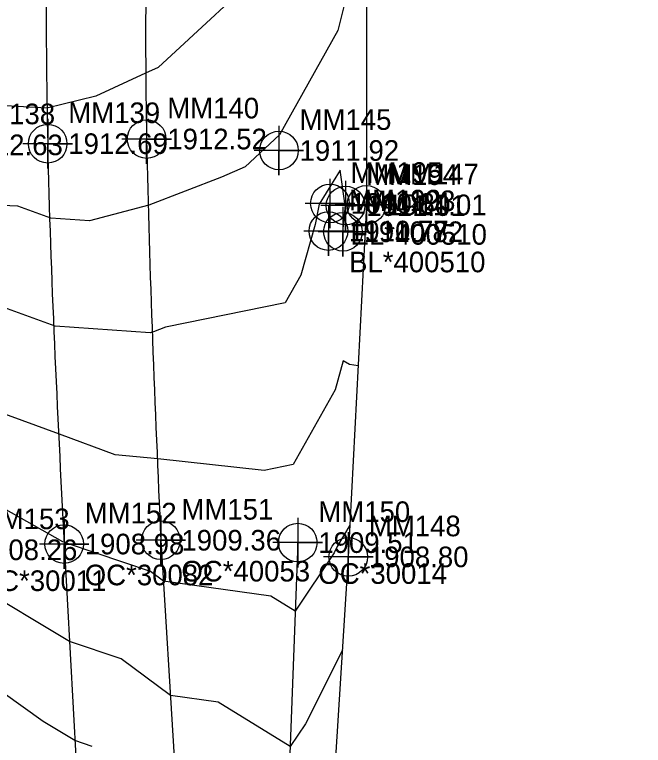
# Model space of a CAD drawing. Extents: x 1004378 to 1005103, y 553854 to 554288.
# Drawn here: x 1005009.8 to 1005086, y 554030.8 to 554119.4 of the extents above; entities that cross this region are included whole.
import ezdxf

# ---------------------------------------------------------------- set-up
doc = ezdxf.new("R2010")
doc.units = 0
for name, color, linetype in [('DTM Contours Major', 7, 'Continuous'), ('DTM Contours Minor', 7, 'Continuous'), ('Exist DTM Breakline', 7, 'Continuous'), ('Exist DTM Breakline Cogo Comment', 7, 'Continuous'), ('Exist DTM Breakline Cogo Elevation', 7, 'Continuous'), ('Exist DTM Breakline Cogo Number', 7, 'Continuous'), ('Exist DTM Breakline Cogo Point CELL', 7, 'Continuous'), ('Exist DTM Crownline', 7, 'Continuous'), ('Exist DTM Crownline Cogo Comment', 7, 'Continuous'), ('Exist DTM Crownline Cogo Elevation', 7, 'Continuous'), ('Exist DTM Crownline Cogo Number', 7, 'Continuous'), ('Exist DTM Crownline Cogo Point CELL', 7, 'Continuous'), ('Exist Roads EOP', 7, 'Continuous'), ('Exist Roads EOP Cogo Comment', 7, 'Continuous'), ('Exist Roads EOP Cogo Elevation', 7, 'Continuous'), ('Exist Roads EOP Cogo Number', 7, 'Continuous'), ('Exist Roads EOP Cogo Point CELL', 7, 'Continuous')]:
    doc.layers.add(name, color=color, linetype=linetype)

msp = doc.modelspace()

# ---------------------------------------------------------------- linework, layer by layer
at = {"layer": 'DTM Contours Major'}
msp.add_lwpolyline([(1005051.433, 554076.836), (1005050.379, 554076.997), (1005049.638, 554077.419), (1005048.654, 554073.906), (1005043.562, 554064.845), (1005040.05, 554064.129), (1005027.148, 554065.55), (1005021.967, 554066.02), (1005015.22, 554068.538), (1005006.107, 554071.836), (1005002.083, 554074.095), (1005000.368, 554076.389), (1005000.016, 554076.907), (1004996.136, 554080.152), (1004993.696, 554082.636), (1004992.74, 554083.442), (1004991.884, 554081.943), (1004990.65, 554081.337), (1004990.87, 554080.789), (1004991.142, 554080.251), (1004992.761, 554070.753), (1004992.29, 554066.815), (1004992.25, 554064.983), (1004991.398, 554057.275)], dxfattribs=at)
at = {"layer": 'DTM Contours Minor'}
for points in [[(1005052.451, 554131.423), (1005048.992, 554117.484), (1005041.887, 554104.823), (1005037.717, 554100.961), (1005034.877, 554099.678), (1005026.061, 554096.307), (1005018.838, 554094.398), (1005014.143, 554094.731), (1005010.132, 554096.182), (1005001.278, 554096.56)], [(1005041.535, 554126.294), (1005027.186, 554113.002), (1005025.646, 554112.306), (1005019.626, 554109.515), (1005013.669, 554108.071), (1005006.504, 554108.468), (1005001.004, 554108.005), (1004994.526, 554114.001), (1004990.716, 554115.591), (1004987.329, 554111.605), (1004985.839, 554106.502), (1004985.665, 554106.048), (1004985.362, 554104.451), (1004983.277, 554088.12), (1004983.322, 554088.07), (1004988.078, 554078.655), (1004989.286, 554071.569), (1004988.935, 554068.632), (1004988.827, 554063.674), (1004986.946, 554046.675), (1004985.61, 554041.811), (1004986.291, 554040.195), (1004985.892, 554032.658), (1004985.548, 554017.288)], [(1005052.429, 554096.185), (1005052.32, 554096.202), (1005049.904, 554096.144), (1005049.861, 554096.167), (1005049.846, 554096.257), (1005049.276, 554100.535), (1005046.713, 554096.403), (1005046.211, 554093.964), (1005044.49, 554087.817), (1005042.6, 554084.453), (1005028.071, 554081.489), (1005026.605, 554080.928), (1005026.192, 554080.819), (1005014.682, 554081.634), (1005004.85, 554085.192)], [(1005050.437, 554057.486), (1005048.879, 554054.931), (1005048.518, 554054.142), (1005043.793, 554047.065), (1005040.855, 554048.876), (1005027.803, 554050.713), (1005026.234, 554051.882), (1005016.31, 554055.236), (1005015.759, 554055.441), (1005015.604, 554055.497), (1005002.486, 554062.863), (1004996.894, 554070.341), (1004995.745, 554072.029), (1004993.918, 554073.557), (1004993.443, 554073.279), (1004993.92, 554070.481), (1004993.409, 554066.21), (1004993.392, 554065.419), (1004990.679, 554040.901), (1004990.057, 554038.638), (1004990.374, 554037.886), (1004989.848, 554027.938)], [(1005049.523, 554042.345), (1005045.034, 554033.434), (1005043.176, 554030.651), (1005034.444, 554036.034), (1005028.658, 554036.849), (1005022.704, 554041.282), (1005016.415, 554043.408), (1005004.921, 554050.257), (1005002.926, 554051.684), (1005001.954, 554052.767), (1004994.229, 554063.106), (1004991.612, 554039.458), (1004991.169, 554037.845), (1004991.395, 554037.308), (1004990.837, 554026.758)], [(1005019.174, 554030.683), (1005017.072, 554031.393), (1005013.231, 554033.682), (1005003.473, 554040.664), (1004998.719, 554045.96), (1004994.107, 554052.132), (1004992.545, 554038.014), (1004992.281, 554037.051), (1004992.416, 554036.731), (1004991.826, 554025.578)]]:
    msp.add_lwpolyline(points, dxfattribs=at)
at = {"layer": 'Exist DTM Breakline'}
msp.add_line((1005027.497, 554055.674), (1005030.119, 554013.168), dxfattribs=at)
for points in [[(1005086.044, 554233.622), (1005066.807, 554200.26), (1005058.407, 554172.308), (1005052.455, 554140.645), (1005052.437, 554096.336), (1005050.24, 554053.656), (1005047.48, 554010.1), (1005047.57, 553964.54), (1005045.226, 553915.523), (1005033.752, 553871.735)], [(1005047.836, 554093.162), (1005049.592, 554093.078), (1005049.914, 554096.247), (1005048.016, 554096.507)]]:
    msp.add_lwpolyline(points, dxfattribs=at)
msp.add_spline([(1005062.556, 554249.275), (1005041.97, 554212.824), (1005032.11, 554179.915), (1005026.833, 554146.301), (1005025.779, 554104.318), (1005027.497, 554055.674)], degree=3, dxfattribs=at)
at = {"layer": 'Exist DTM Breakline Cogo Point CELL'}
for points in [[(1005025.779, 554107.318), (1005025.779, 554101.318), (1005025.779, 554104.318), (1005028.779, 554104.318), (1005022.779, 554104.318)], [(1005048.016, 554099.507), (1005048.016, 554093.507), (1005048.016, 554096.507), (1005051.016, 554096.507), (1005045.016, 554096.507)], [(1005049.914, 554099.247), (1005049.914, 554093.247), (1005049.914, 554096.247), (1005052.914, 554096.247), (1005046.914, 554096.247)], [(1005052.437, 554099.336), (1005052.437, 554093.336), (1005052.437, 554096.336), (1005055.437, 554096.336), (1005049.437, 554096.336)], [(1005047.836, 554096.162), (1005047.836, 554090.162), (1005047.836, 554093.162), (1005050.836, 554093.162), (1005044.836, 554093.162)], [(1005049.592, 554096.078), (1005049.592, 554090.078), (1005049.592, 554093.078), (1005052.592, 554093.078), (1005046.592, 554093.078)], [(1005027.497, 554058.674), (1005027.497, 554052.674), (1005027.497, 554055.674), (1005030.497, 554055.674), (1005024.497, 554055.674)], [(1005050.24, 554056.656), (1005050.24, 554050.656), (1005050.24, 554053.656), (1005053.24, 554053.656), (1005047.24, 554053.656)]]:
    msp.add_lwpolyline(points, dxfattribs=at)
for centre in [(1005025.779, 554104.318), (1005048.016, 554096.507), (1005049.914, 554096.247), (1005052.437, 554096.336), (1005047.836, 554093.162), (1005049.592, 554093.078), (1005027.497, 554055.674), (1005050.24, 554053.656)]:
    msp.add_circle(centre, 2.344, dxfattribs=at)
at = {"layer": 'Exist DTM Crownline'}
msp.add_line((1005015.769, 554055.214), (1005018.108, 554012.47), dxfattribs=at)
msp.add_spline([(1005050.587, 554258.044), (1005028.479, 554219.945), (1005017.046, 554183.931), (1005013.967, 554147.492), (1005013.771, 554103.753), (1005015.769, 554055.214)], degree=3, dxfattribs=at)
at = {"layer": 'Exist DTM Crownline Cogo Point CELL'}
for points in [[(1005013.771, 554106.753), (1005013.771, 554100.753), (1005013.771, 554103.753), (1005016.771, 554103.753), (1005010.771, 554103.753)], [(1005015.769, 554058.214), (1005015.769, 554052.214), (1005015.769, 554055.214), (1005018.769, 554055.214), (1005012.769, 554055.214)]]:
    msp.add_lwpolyline(points, dxfattribs=at)
for centre in [(1005013.771, 554103.753), (1005015.769, 554055.214)]:
    msp.add_circle(centre, 2.344, dxfattribs=at)
at = {"layer": 'Exist Roads EOP'}
msp.add_line((1005044.105, 554055.385), (1005042.505, 554012.793), dxfattribs=at)
msp.add_spline([(1005026.381, 554243.671), (1005017.049, 554225.785), (1005004.478, 554185.698), (1005001.445, 554147.868), (1005001.025, 554103.612), (1005002.785, 554054.517)], degree=3, dxfattribs=at)
at = {"layer": 'Exist Roads EOP Cogo Point CELL'}
for points in [[(1005041.827, 554105.929), (1005041.827, 554099.929), (1005041.827, 554102.929), (1005044.827, 554102.929), (1005038.827, 554102.929)], [(1005044.105, 554058.385), (1005044.105, 554052.385), (1005044.105, 554055.385), (1005047.105, 554055.385), (1005041.105, 554055.385)]]:
    msp.add_lwpolyline(points, dxfattribs=at)
for centre in [(1005041.827, 554102.929), (1005044.105, 554055.385)]:
    msp.add_circle(centre, 2.344, dxfattribs=at)

# ---------------------------------------------------------------- texts
at = {"layer": 'Exist DTM Breakline Cogo Comment'}
for s, p in [('EL*400510', (1005050.516, 554091.507)), ('BL*400510', (1005050.336, 554088.162)), ('OC*40053', (1005029.997, 554050.674))]:
    msp.add_text(s, height=2.5, dxfattribs=at).set_placement(p)
at = {"layer": 'Exist DTM Breakline Cogo Elevation'}
for s, p in [('1912.52', (1005028.279, 554103.068)), ('1910.84', (1005050.516, 554095.257)), ('1911.01', (1005052.414, 554094.997)), ('1911.01', (1005054.937, 554095.086)), ('1910.77', (1005050.336, 554091.912)), ('1910.82', (1005052.092, 554091.828)), ('1909.36', (1005029.997, 554054.424)), ('1908.80', (1005052.74, 554052.406))]:
    msp.add_text(s, height=2.5, dxfattribs=at).set_placement(p)
at = {"layer": 'Exist DTM Breakline Cogo Number'}
for s, p in [('MM140', (1005028.279, 554106.818)), ('MM195', (1005050.516, 554099.007)), ('MM194', (1005052.414, 554098.747)), ('MM147', (1005054.937, 554098.836)), ('MM192', (1005050.336, 554095.662)), ('MM193', (1005052.092, 554095.578)), ('MM151', (1005029.997, 554058.174)), ('MM148', (1005052.74, 554056.156))]:
    msp.add_text(s, height=2.5, dxfattribs=at).set_placement(p)
at = {"layer": 'Exist DTM Crownline Cogo Comment'}
msp.add_text('OC*30082', height=2.5, dxfattribs=at).set_placement((1005018.269, 554050.214))
at = {"layer": 'Exist DTM Crownline Cogo Elevation'}
for s, p in [('1912.69', (1005016.271, 554102.503)), ('1908.98', (1005018.269, 554053.964))]:
    msp.add_text(s, height=2.5, dxfattribs=at).set_placement(p)
at = {"layer": 'Exist DTM Crownline Cogo Number'}
for s, p in [('MM139', (1005016.271, 554106.253)), ('MM152', (1005018.269, 554057.714))]:
    msp.add_text(s, height=2.5, dxfattribs=at).set_placement(p)
at = {"layer": 'Exist Roads EOP Cogo Comment'}
for s, p in [('OC*30014', (1005046.605, 554050.385)), ('OC*30011', (1005005.285, 554049.517))]:
    msp.add_text(s, height=2.5, dxfattribs=at).set_placement(p)
at = {"layer": 'Exist Roads EOP Cogo Elevation'}
for s, p in [('1912.63', (1005003.525, 554102.362)), ('1911.92', (1005044.327, 554101.679)), ('1909.51', (1005046.605, 554054.135)), ('1908.26', (1005005.285, 554053.267))]:
    msp.add_text(s, height=2.5, dxfattribs=at).set_placement(p)
at = {"layer": 'Exist Roads EOP Cogo Number'}
for s, p in [('MM138', (1005003.525, 554106.112)), ('MM145', (1005044.327, 554105.429)), ('MM150', (1005046.605, 554057.885)), ('MM153', (1005005.285, 554057.017))]:
    msp.add_text(s, height=2.5, dxfattribs=at).set_placement(p)

doc.saveas('drawing.dxf')
